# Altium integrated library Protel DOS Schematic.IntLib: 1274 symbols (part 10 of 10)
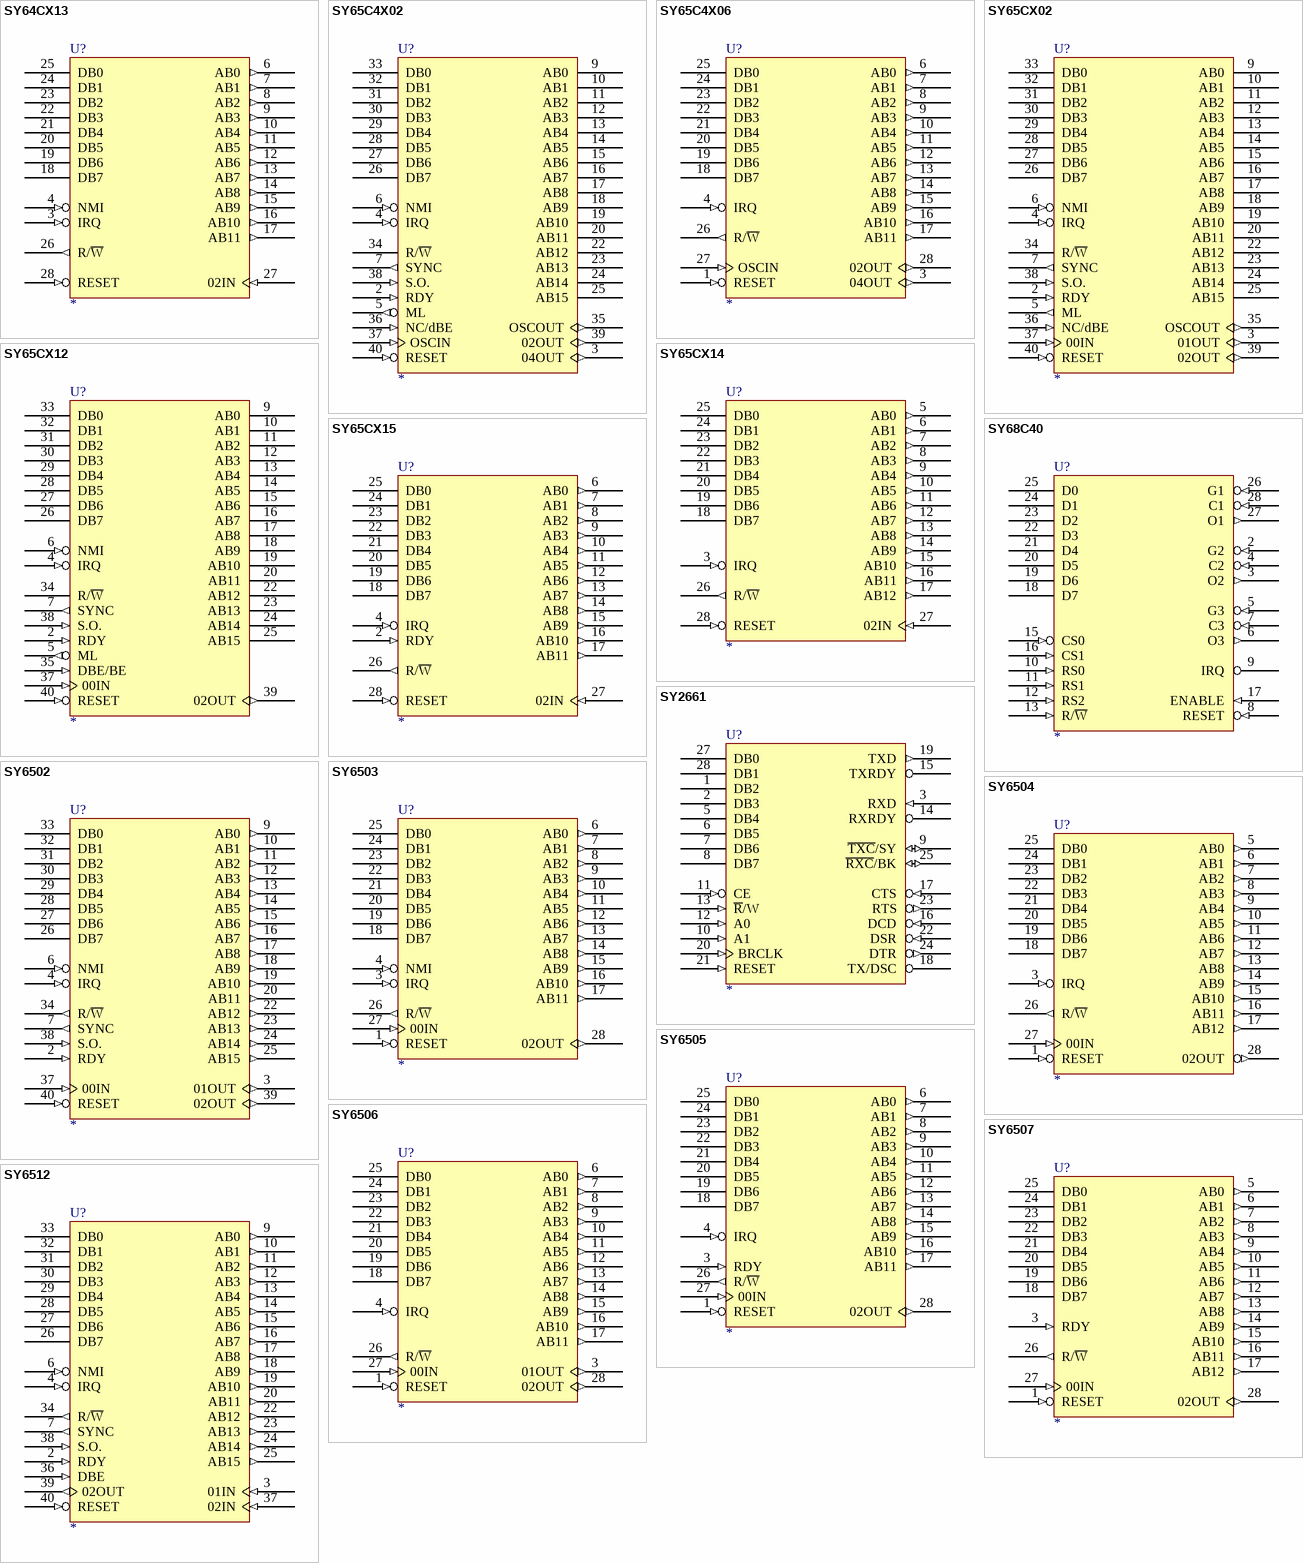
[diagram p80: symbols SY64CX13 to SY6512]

## SY6504
designator U?
footprint DIP-28
pins: 1 RESET (in), 2 GND (power) hidden to GND, 3 IRQ (in), 4 VCC (power) hidden to VCC, 5 AB0 (out), 6 AB1 (out), 7 AB2 (out), 8 AB3 (out), 9 AB4 (out), 10 AB5 (out), 11 AB6 (out), 12 AB7 (out), 13 AB8 (out), 14 AB9 (out), 15 AB10 (out), 16 AB11 (out), 17 AB12 (out), 18 DB7 (hiz), 19 DB6 (hiz), 20 DB5 (hiz), 21 DB4 (hiz), 22 DB3 (hiz), 23 DB2 (hiz), 24 DB1 (hiz), 25 DB0 (hiz), 26 R/~{W} (out), 27 00IN (in), 28 02OUT (out)
2 alternate drawings of the same symbol

## SY6505
designator U?
footprint DIP-28
pins: 1 RESET (in), 2 GND (power) hidden to GND, 3 RDY (in), 4 IRQ (in), 5 VCC (power) hidden to VCC, 6 AB0 (out), 7 AB1 (out), 8 AB2 (out), 9 AB3 (out), 10 AB4 (out), 11 AB5 (out), 12 AB6 (out), 13 AB7 (out), 14 AB8 (out), 15 AB9 (out), 16 AB10 (out), 17 AB11 (out), 18 DB7 (hiz), 19 DB6 (hiz), 20 DB5 (hiz), 21 DB4 (hiz), 22 DB3 (hiz), 23 DB2 (hiz), 24 DB1 (hiz), 25 DB0 (hiz), 26 R/~{W} (out), 27 00IN (in), 28 02OUT (out)
2 alternate drawings of the same symbol

## SY6506
designator U?
footprint DIP-28
pins: 1 RESET (in), 2 GND (power) hidden to GND, 3 01OUT (out), 4 IRQ (in), 5 VCC (power) hidden to VCC, 6 AB0 (out), 7 AB1 (out), 8 AB2 (out), 9 AB3 (out), 10 AB4 (out), 11 AB5 (out), 12 AB6 (out), 13 AB7 (out), 14 AB8 (out), 15 AB9 (out), 16 AB10 (out), 17 AB11 (out), 18 DB7 (hiz), 19 DB6 (hiz), 20 DB5 (hiz), 21 DB4 (hiz), 22 DB3 (hiz), 23 DB2 (hiz), 24 DB1 (hiz), 25 DB0 (hiz), 26 R/~{W} (out), 27 00IN (in), 28 02OUT (out)
2 alternate drawings of the same symbol

## SY6507
designator U?
footprint DIP-28
pins: 1 RESET (in), 2 GND (power) hidden to GND, 3 RDY (in), 4 VCC (power) hidden to VCC, 5 AB0 (out), 6 AB1 (out), 7 AB2 (out), 8 AB3 (out), 9 AB4 (out), 10 AB5 (out), 11 AB6 (out), 12 AB7 (out), 13 AB8 (out), 14 AB9 (out), 15 AB10 (out), 16 AB11 (out), 17 AB12 (out), 18 DB7 (hiz), 19 DB6 (hiz), 20 DB5 (hiz), 21 DB4 (hiz), 22 DB3 (hiz), 23 DB2 (hiz), 24 DB1 (hiz), 25 DB0 (hiz), 26 R/~{W} (out), 27 00IN (in), 28 02OUT (out)
2 alternate drawings of the same symbol

## SY6512
designator U?
footprint DIP-40
pins: 1 GND (power) hidden to GND, 2 RDY (in), 3 01IN (in), 4 IRQ (in), 5 GND (power) hidden to GND, 6 NMI (in), 7 SYNC (out), 8 VCC (power) hidden to VCC, 9 AB0 (out), 10 AB1 (out), 11 AB2 (out), 12 AB3 (out), 13 AB4 (out), 14 AB5 (out), 15 AB6 (out), 16 AB7 (out), 17 AB8 (out), 18 AB9 (out), 19 AB10 (out), 20 AB11 (out), 21 GND (power) hidden to GND, 22 AB12 (out), 23 AB13 (out), 24 AB14 (out), 25 AB15 (out), 26 DB7 (hiz), 27 DB6 (hiz), 28 DB5 (hiz), 29 DB4 (hiz), 30 DB3 (hiz), 31 DB2 (hiz), 32 DB1 (hiz), 33 DB0 (hiz), 34 R/~{W} (out), 36 DBE (in), 37 02IN (in), 38 S.O. (in), 39 02OUT (out), 40 RESET (in)
2 alternate drawings of the same symbol

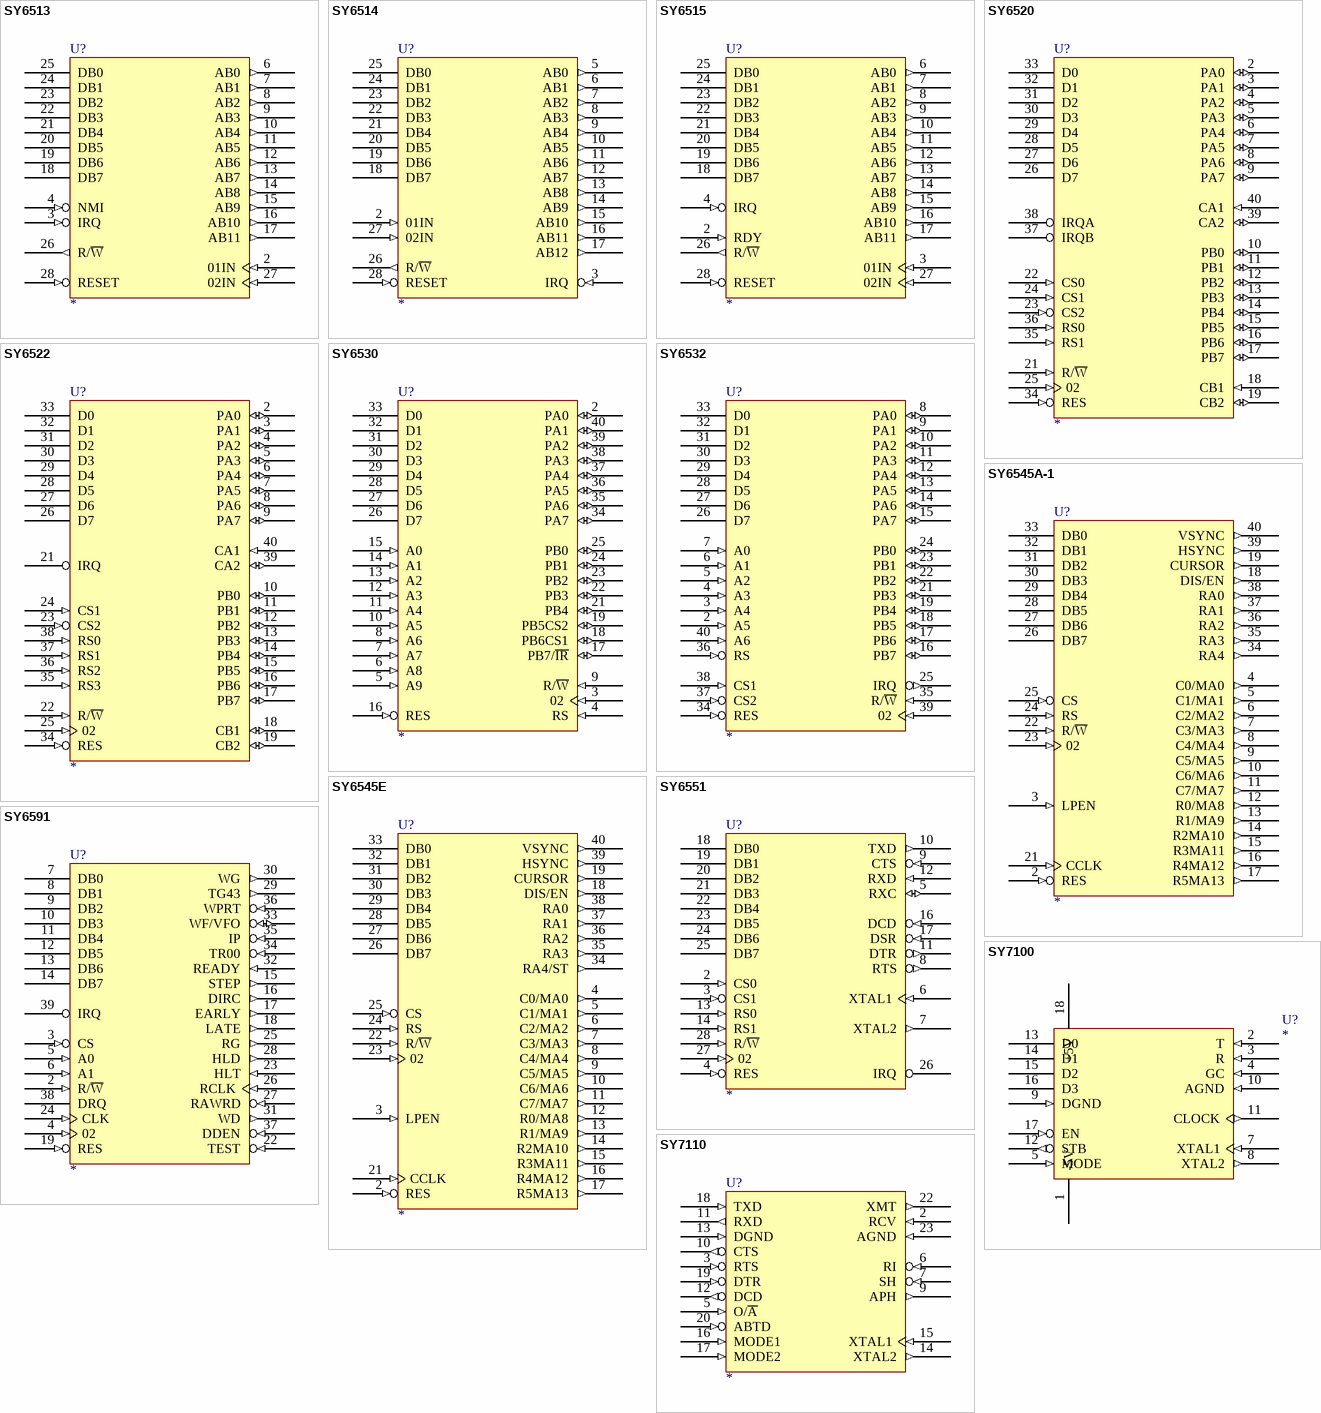
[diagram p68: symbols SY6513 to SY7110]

## SY6513
designator U?
footprint DIP-28
pins: 1 GND (power) hidden to GND, 2 01IN (in), 3 IRQ (in), 4 NMI (in), 5 VCC (power) hidden to VCC, 6 AB0 (out), 7 AB1 (out), 8 AB2 (out), 9 AB3 (out), 10 AB4 (out), 11 AB5 (out), 12 AB6 (out), 13 AB7 (out), 14 AB8 (out), 15 AB9 (out), 16 AB10 (out), 17 AB11 (out), 18 DB7 (hiz), 19 DB6 (hiz), 20 DB5 (hiz), 21 DB4 (hiz), 22 DB3 (hiz), 23 DB2 (hiz), 24 DB1 (hiz), 25 DB0 (hiz), 26 R/~{W} (out), 27 02IN (in), 28 RESET (in)
2 alternate drawings of the same symbol

## SY6514
designator U?
footprint DIP-28
pins: 1 GND (power) hidden to GND, 2 01IN (in), 3 IRQ (in), 4 VCC (power) hidden to VCC, 5 AB0 (out), 6 AB1 (out), 7 AB2 (out), 8 AB3 (out), 9 AB4 (out), 10 AB5 (out), 11 AB6 (out), 12 AB7 (out), 13 AB8 (out), 14 AB9 (out), 15 AB10 (out), 16 AB11 (out), 17 AB12 (out), 18 DB7 (hiz), 19 DB6 (hiz), 20 DB5 (hiz), 21 DB4 (hiz), 22 DB3 (hiz), 23 DB2 (hiz), 24 DB1 (hiz), 25 DB0 (hiz), 26 R/~{W} (out), 27 02IN (in), 28 RESET (in)
2 alternate drawings of the same symbol

## SY6515
designator U?
footprint DIP-28
pins: 1 GND (power) hidden to GND, 2 RDY (in), 3 01IN (in), 4 IRQ (in), 5 VCC (power) hidden to VCC, 6 AB0 (out), 7 AB1 (out), 8 AB2 (out), 9 AB3 (out), 10 AB4 (out), 11 AB5 (out), 12 AB6 (out), 13 AB7 (out), 14 AB8 (out), 15 AB9 (out), 16 AB10 (out), 17 AB11 (out), 18 DB7 (hiz), 19 DB6 (hiz), 20 DB5 (hiz), 21 DB4 (hiz), 22 DB3 (hiz), 23 DB2 (hiz), 24 DB1 (hiz), 25 DB0 (hiz), 26 R/~{W} (out), 27 02IN (in), 28 RESET (in)
2 alternate drawings of the same symbol

## SY6520
designator U?
footprint DIP-40
pins: 1 GND (power) hidden to GND, 2 PA0 (io), 3 PA1 (io), 4 PA2 (io), 5 PA3 (io), 6 PA4 (io), 7 PA5 (io), 8 PA6 (io), 9 PA7 (io), 10 PB0 (io), 11 PB1 (io), 12 PB2 (io), 13 PB3 (io), 14 PB4 (io), 15 PB5 (io), 16 PB6 (io), 17 PB7 (io), 18 CB1 (in), 19 CB2 (io), 20 VCC (power) hidden to VCC, 21 R/~{W} (in), 22 CS0 (in), 23 CS2 (in), 24 CS1 (in), 25 02 (in), 26 D7 (hiz), 27 D6 (hiz), 28 D5 (hiz), 29 D4 (hiz), 30 D3 (hiz), 31 D2 (hiz), 32 D1 (hiz), 33 D0 (hiz), 34 RES (in), 35 RS1 (in), 36 RS0 (in), 37 IRQB (oc), 38 IRQA (oc), 39 CA2 (io), 40 CA1 (in)
2 alternate drawings of the same symbol

## SY6522
designator U?
footprint DIP-40
pins: 1 GND (power) hidden to GND, 2 PA0 (io), 3 PA1 (io), 4 PA2 (io), 5 PA3 (io), 6 PA4 (io), 7 PA5 (io), 8 PA6 (io), 9 PA7 (io), 10 PB0 (io), 11 PB1 (io), 12 PB2 (io), 13 PB3 (io), 14 PB4 (io), 15 PB5 (io), 16 PB6 (io), 17 PB7 (io), 18 CB1 (io), 19 CB2 (io), 20 VCC (power) hidden to VCC, 21 IRQ (oc), 22 R/~{W} (in), 23 CS2 (in), 24 CS1 (in), 25 02 (in), 26 D7 (hiz), 27 D6 (hiz), 28 D5 (hiz), 29 D4 (hiz), 30 D3 (hiz), 31 D2 (hiz), 32 D1 (hiz), 33 D0 (hiz), 34 RES (in), 35 RS3 (in), 36 RS2 (in), 37 RS1 (in), 38 RS0 (in), 39 CA2 (io), 40 CA1 (in)
2 alternate drawings of the same symbol

## SY6530
designator U?
footprint DIP-40
pins: 1 GND (power) hidden to GND, 2 PA0 (io), 3 02 (in), 4 RS (in), 5 A9 (in), 6 A8 (in), 7 A7 (in), 8 A6 (in), 9 R/~{W} (in), 10 A5 (in), 11 A4 (in), 12 A3 (in), 13 A2 (in), 14 A1 (in), 15 A0 (in), 16 RES (in), 17 PB7/~{IR} (io), 18 PB6CS1 (io), 19 PB5CS2 (io), 20 VCC (power) hidden to VCC, 21 PB4 (io), 22 PB3 (io), 23 PB2 (io), 24 PB1 (io), 25 PB0 (io), 26 D7 (hiz), 27 D6 (hiz), 28 D5 (hiz), 29 D4 (hiz), 30 D3 (hiz), 31 D2 (hiz), 32 D1 (hiz), 33 D0 (hiz), 34 PA7 (io), 35 PA6 (io), 36 PA5 (io), 37 PA4 (io), 38 PA3 (io), 39 PA2 (io), 40 PA1 (io)
2 alternate drawings of the same symbol

## SY6532
designator U?
footprint DIP-40
pins: 1 GND (power) hidden to GND, 2 A5 (in), 3 A4 (in), 4 A3 (in), 5 A2 (in), 6 A1 (in), 7 A0 (in), 8 PA0 (io), 9 PA1 (io), 10 PA2 (io), 11 PA3 (io), 12 PA4 (io), 13 PA5 (io), 14 PA6 (io), 15 PA7 (io), 16 PB7 (io), 17 PB6 (io), 18 PB5 (io), 19 PB4 (io), 20 VCC (power) hidden to VCC, 21 PB3 (io), 22 PB2 (io), 23 PB1 (io), 24 PB0 (io), 25 IRQ (out), 26 D7 (hiz), 27 D6 (hiz), 28 D5 (hiz), 29 D4 (hiz), 30 D3 (hiz), 31 D2 (hiz), 32 D1 (hiz), 33 D0 (hiz), 34 RES (in), 35 R/~{W} (in), 36 RS (in), 37 CS2 (in), 38 CS1 (in), 39 02 (in), 40 A6 (in)
2 alternate drawings of the same symbol

## SY6545A-1
designator U?
footprint DIP-40
pins: 1 GND (power) hidden to GND, 2 RES (in), 3 LPEN (in), 4 C0/MA0 (out), 5 C1/MA1 (out), 6 C2/MA2 (out), 7 C3/MA3 (out), 8 C4/MA4 (out), 9 C5/MA5 (out), 10 C6/MA6 (out), 11 C7/MA7 (out), 12 R0/MA8 (out), 13 R1/MA9 (out), 14 R2MA10 (out), 15 R3MA11 (out), 16 R4MA12 (out), 17 R5MA13 (out), 18 DIS/EN (out), 19 CURSOR (out), 20 VCC (power) hidden to VCC, 21 CCLK (in), 22 R/~{W} (in), 23 02 (in), 24 RS (in), 25 CS (in), 26 DB7 (hiz), 27 DB6 (hiz), 28 DB5 (hiz), 29 DB4 (hiz), 30 DB3 (hiz), 31 DB2 (hiz), 32 DB1 (hiz), 33 DB0 (hiz), 34 RA4 (out), 35 RA3 (out), 36 RA2 (out), 37 RA1 (out), 38 RA0 (out), 39 HSYNC (out), 40 VSYNC (out)
2 alternate drawings of the same symbol

## SY6545E
designator U?
footprint DIP-40
pins: 1 GND (power) hidden to GND, 2 RES (in), 3 LPEN (in), 4 C0/MA0 (out), 5 C1/MA1 (out), 6 C2/MA2 (out), 7 C3/MA3 (out), 8 C4/MA4 (out), 9 C5/MA5 (out), 10 C6/MA6 (out), 11 C7/MA7 (out), 12 R0/MA8 (out), 13 R1/MA9 (out), 14 R2MA10 (out), 15 R3MA11 (out), 16 R4MA12 (out), 17 R5MA13 (out), 18 DIS/EN (out), 19 CURSOR (out), 20 VCC (power) hidden to VCC, 21 CCLK (in), 22 R/~{W} (in), 23 02 (in), 24 RS (in), 25 CS (in), 26 DB7 (hiz), 27 DB6 (hiz), 28 DB5 (hiz), 29 DB4 (hiz), 30 DB3 (hiz), 31 DB2 (hiz), 32 DB1 (hiz), 33 DB0 (hiz), 34 RA4/ST (out), 35 RA3 (out), 36 RA2 (out), 37 RA1 (out), 38 RA0 (out), 39 HSYNC (out), 40 VSYNC (out)
2 alternate drawings of the same symbol

## SY6551
designator U?
footprint DIP-28
pins: 1 GND (power) hidden to GND, 2 CS0 (in), 3 CS1 (in), 4 RES (in), 5 RXC (io), 6 XTAL1 (in), 7 XTAL2 (out), 8 RTS (out), 9 CTS (in), 10 TXD (out), 11 DTR (out), 12 RXD (in), 13 RS0 (in), 14 RS1 (in), 15 VCC (power) hidden to VCC, 16 DCD (in), 17 DSR (in), 18 DB0 (hiz), 19 DB1 (hiz), 20 DB2 (hiz), 21 DB3 (hiz), 22 DB4 (hiz), 23 DB5 (hiz), 24 DB6 (hiz), 25 DB7 (hiz), 26 IRQ (oc), 27 02 (in), 28 R/~{W} (in)
2 alternate drawings of the same symbol

## SY6591
designator U?
footprint DIP-40
pins: 2 R/~{W} (in), 3 CS (in), 4 02 (in), 5 A0 (in), 6 A1 (in), 7 DB0 (hiz), 8 DB1 (hiz), 9 DB2 (hiz), 10 DB3 (hiz), 11 DB4 (hiz), 12 DB5 (hiz), 13 DB6 (hiz), 14 DB7 (hiz), 15 STEP (out), 16 DIRC (out), 17 EARLY (out), 18 LATE (out), 19 RES (in), 20 GND (power) hidden to GND, 21 VCC (power) hidden to VCC, 22 TEST (in), 23 HLT (in), 24 CLK (in), 25 RG (out), 26 RCLK (in), 27 RAWRD (in), 28 HLD (out), 29 TG43 (out), 30 WG (out), 31 WD (out), 32 READY (in), 33 WF/VFO (io), 34 TR00 (in), 35 IP (in), 36 WPRT (in), 37 DDEN (in), 38 DRQ (oc), 39 IRQ (oc)
2 alternate drawings of the same symbol

## SY7100
designator U?
footprint DIP-18
pins: 1 -5V (power), 2 T (in), 3 R (in), 4 GC (in), 5 MODE (in), 7 XTAL1 (in), 8 XTAL2 (out), 9 DGND (in), 10 AGND (in), 11 CLOCK (out), 12 STB (out), 13 D0 (hiz), 14 D1 (hiz), 15 D2 (hiz), 16 D3 (hiz), 17 EN (in), 18 +5V (power)
2 alternate drawings of the same symbol

## SY7110
designator U?
footprint DIP-24
pins: 2 RCV (in), 3 RTS (in), 5 O/~{A} (in), 6 RI (in), 7 SH (in), 8 VCC (power) hidden to VCC, 9 APH (out), 10 CTS (out), 11 RXD (out), 12 DCD (out), 13 DGND (in), 14 XTAL2 (out), 15 XTAL1 (in), 16 MODE1 (in), 17 MODE2 (in), 18 TXD (in), 19 DTR (in), 20 ABTD (in), 22 XMT (out), 23 AGND (in), 24 GND (power) hidden to GND
2 alternate drawings of the same symbol


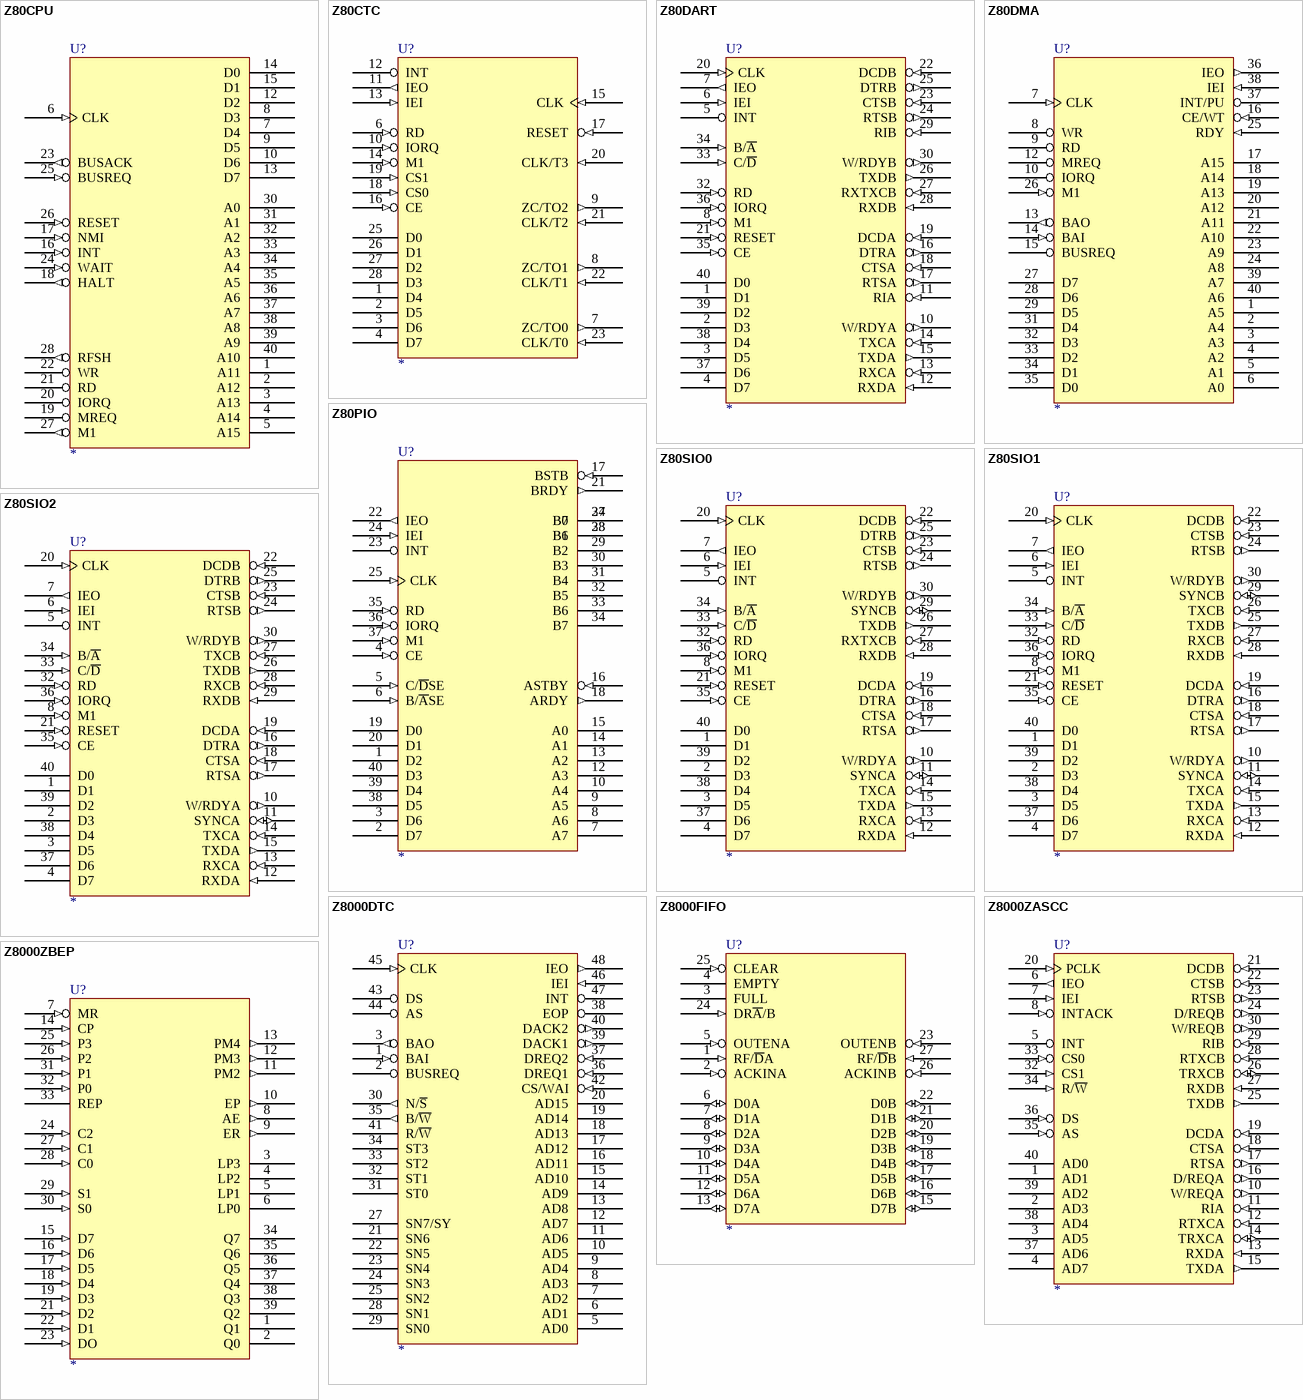
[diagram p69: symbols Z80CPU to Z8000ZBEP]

## Z80CPU
designator U?
footprint DIP-40
pins: 1 A11 (hiz), 2 A12 (hiz), 3 A13 (hiz), 4 A14 (hiz), 5 A15 (hiz), 6 CLK (in), 7 D4 (hiz), 8 D3 (hiz), 9 D5 (hiz), 10 D6 (hiz), 11 VCC (power) hidden to VCC, 12 D2 (hiz), 13 D7 (hiz), 14 D0 (hiz), 15 D1 (hiz), 16 INT (in), 17 NMI (in), 18 HALT (out), 19 MREQ (hiz), 20 IORQ (hiz), 21 RD (hiz), 22 WR (hiz), 23 BUSACK (out), 24 WAIT (in), 25 BUSREQ (in), 26 RESET (in), 27 M1 (out), 28 RFSH (out), 29 GND (power) hidden to GND, 30 A0 (hiz), 31 A1 (hiz), 32 A2 (hiz), 33 A3 (hiz), 34 A4 (hiz), 35 A5 (hiz), 36 A6 (hiz), 37 A7 (hiz), 38 A8 (hiz), 39 A9 (hiz), 40 A10 (hiz)
2 alternate drawings of the same symbol

## Z80CTC
designator U?
footprint DIP-28
pins: 1 D4 (hiz), 2 D5 (hiz), 3 D6 (hiz), 4 D7 (hiz), 5 GND (power) hidden to GND, 6 RD (in), 7 ZC/TO0 (out), 8 ZC/TO1 (out), 9 ZC/TO2 (out), 10 IORQ (in), 11 IEO (out), 12 INT (oc), 13 IEI (in), 14 M1 (in), 15 CLK (in), 16 CE (in), 17 RESET (in), 18 CS0 (in), 19 CS1 (in), 20 CLK/T3 (in), 21 CLK/T2 (in), 22 CLK/T1 (in), 23 CLK/T0 (in), 24 VCC (power) hidden to VCC, 25 D0 (hiz), 26 D1 (hiz), 27 D2 (hiz), 28 D3 (hiz)
2 alternate drawings of the same symbol

## Z80DART
designator U?
footprint DIP-40
pins: 1 D1 (hiz), 2 D3 (hiz), 3 D5 (hiz), 4 D7 (hiz), 5 INT (oc), 6 IEI (in), 7 IEO (out), 8 M1 (in), 9 VCC (power) hidden to VCC, 10 W/RDYA (out), 11 RIA (in), 12 RXDA (in), 13 RXCA (in), 14 TXCA (in), 15 TXDA (out), 16 DTRA (out), 17 RTSA (out), 18 CTSA (in), 19 DCDA (in), 20 CLK (in), 21 RESET (in), 22 DCDB (in), 23 CTSB (in), 24 RTSB (out), 25 DTRB (out), 26 TXDB (out), 27 RXTXCB (in), 28 RXDB (in), 29 RIB (in), 30 W/RDYB (out), 31 GND (power) hidden to GND, 32 RD (in), 33 C/~{D} (in), 34 B/~{A} (in), 35 CE (in), 36 IORQ (in), 37 D6 (hiz), 38 D4 (hiz), 39 D2 (hiz), 40 D0 (hiz)
2 alternate drawings of the same symbol

## Z80DMA
designator U?
footprint DIP-40
pins: 1 A5 (hiz), 2 A4 (hiz), 3 A3 (hiz), 4 A2 (hiz), 5 A1 (hiz), 6 A0 (hiz), 7 CLK (in), 8 WR (hiz), 9 RD (hiz), 10 IORQ (hiz), 11 VCC (power) hidden to VCC, 12 MREQ (hiz), 13 BAO (out), 14 BAI (in), 15 BUSREQ (oc), 16 CE/WT (in), 17 A15 (hiz), 18 A14 (hiz), 19 A13 (hiz), 20 A12 (hiz), 21 A11 (hiz), 22 A10 (hiz), 23 A9 (hiz), 24 A8 (hiz), 25 RDY (in), 26 M1 (in), 27 D7 (hiz), 28 D6 (hiz), 29 D5 (hiz), 30 GND (power) hidden to GND, 31 D4 (hiz), 32 D3 (hiz), 33 D2 (hiz), 34 D1 (hiz), 35 D0 (hiz), 36 IEO (out), 37 INT/PU (oc), 38 IEI (in), 39 A7 (hiz), 40 A6 (hiz)
2 alternate drawings of the same symbol

## Z80PIO
designator U?
footprint DIP-40
pins: 1 D2 (hiz), 2 D7 (hiz), 3 D6 (hiz), 4 CE (in), 5 C/~{D}SE (in), 6 B/~{A}SE (in), 7 A7 (hiz), 8 A6 (hiz), 9 A5 (hiz), 10 A4 (hiz), 11 GND (power) hidden to GND, 12 A3 (hiz), 13 A2 (hiz), 14 A1 (hiz), 15 A0 (hiz), 16 ASTBY (in), 17 BSTB (in), 18 ARDY (out), 19 D0 (hiz), 20 D1 (hiz), 21 BRDY (out), 22 IEO (out), 23 INT (oc), 24 IEI (in), 25 CLK (in), 26 VCC (power) hidden to VCC, 27 B0 (hiz), 28 B1 (hiz), 29 B2 (hiz), 30 B3 (hiz), 31 B4 (hiz), 32 B5 (hiz), 33 B6 (hiz), 33 B6 (hiz), 34 B7 (hiz), 34 B7 (hiz), 35 RD (in), 36 IORQ (in), 37 M1 (in), 38 D5 (hiz), 39 D4 (hiz), 40 D3 (hiz)
2 alternate drawings of the same symbol

## Z80SIO0
designator U?
footprint DIP-40
pins: 1 D1 (hiz), 2 D3 (hiz), 3 D5 (hiz), 4 D7 (hiz), 5 INT (oc), 6 IEI (in), 7 IEO (out), 8 M1 (in), 9 VCC (power) hidden to VCC, 10 W/RDYA (out), 11 SYNCA (io), 12 RXDA (in), 13 RXCA (in), 14 TXCA (in), 15 TXDA (out), 16 DTRA (out), 17 RTSA (out), 18 CTSA (in), 19 DCDA (in), 20 CLK (in), 21 RESET (in), 22 DCDB (in), 23 CTSB (in), 24 RTSB (out), 25 DTRB (out), 26 TXDB (out), 27 RXTXCB (in), 28 RXDB (in), 29 SYNCB (io), 30 W/RDYB (out), 31 GND (power) hidden to GND, 32 RD (in), 33 C/~{D} (in), 34 B/~{A} (in), 35 CE (in), 36 IORQ (in), 37 D6 (hiz), 38 D4 (hiz), 39 D2 (hiz), 40 D0 (hiz)
2 alternate drawings of the same symbol

## Z80SIO1
designator U?
footprint DIP-40
pins: 1 D1 (hiz), 2 D3 (hiz), 3 D5 (hiz), 4 D7 (hiz), 5 INT (oc), 6 IEI (in), 7 IEO (out), 8 M1 (in), 9 VCC (power) hidden to VCC, 10 W/RDYA (out), 11 SYNCA (io), 12 RXDA (in), 13 RXCA (in), 14 TXCA (in), 15 TXDA (out), 16 DTRA (out), 17 RTSA (out), 18 CTSA (in), 19 DCDA (in), 20 CLK (in), 21 RESET (in), 22 DCDB (in), 23 CTSB (in), 24 RTSB (out), 25 TXDB (out), 26 TXCB (in), 27 RXCB (in), 28 RXDB (in), 29 SYNCB (io), 30 W/RDYB (out), 31 GND (power) hidden to GND, 32 RD (in), 33 C/~{D} (in), 34 B/~{A} (in), 35 CE (in), 36 IORQ (in), 37 D6 (hiz), 38 D4 (hiz), 39 D2 (hiz), 40 D0 (hiz)
2 alternate drawings of the same symbol

## Z80SIO2
designator U?
footprint DIP-40
pins: 1 D1 (hiz), 2 D3 (hiz), 3 D5 (hiz), 4 D7 (hiz), 5 INT (oc), 6 IEI (in), 7 IEO (out), 8 M1 (in), 9 VCC (power) hidden to VCC, 10 W/RDYA (out), 11 SYNCA (io), 12 RXDA (in), 13 RXCA (in), 14 TXCA (in), 15 TXDA (out), 16 DTRA (out), 17 RTSA (out), 18 CTSA (in), 19 DCDA (in), 20 CLK (in), 21 RESET (in), 22 DCDB (in), 23 CTSB (in), 24 RTSB (out), 25 DTRB (out), 26 TXDB (out), 27 TXCB (in), 28 RXCB (in), 29 RXDB (in), 30 W/RDYB (out), 31 GND (power) hidden to GND, 32 RD (in), 33 C/~{D} (in), 34 B/~{A} (in), 35 CE (in), 36 IORQ (in), 37 D6 (hiz), 38 D4 (hiz), 39 D2 (hiz), 40 D0 (hiz)
2 alternate drawings of the same symbol

## Z8000DTC
designator U?
footprint DIP-48
pins: 1 BAI (in), 2 BUSREQ (hiz), 3 BAO (out), 4 VCC (power) hidden to VCC, 5 AD0 (hiz), 6 AD1 (hiz), 7 AD2 (hiz), 8 AD3 (hiz), 9 AD4 (hiz), 10 AD5 (hiz), 11 AD6 (hiz), 12 AD7 (hiz), 13 AD8 (hiz), 14 AD9 (hiz), 15 AD10 (hiz), 16 AD11 (hiz), 17 AD12 (hiz), 18 AD13 (hiz), 19 AD14 (hiz), 20 AD15 (hiz), 21 SN6 (hiz), 22 SN5 (hiz), 23 SN4 (hiz), 24 SN3 (hiz), 25 SN2 (hiz), 26 GND (power) hidden to GND, 27 SN7/SY (hiz), 28 SN1 (hiz), 29 SN0 (hiz), 30 N/~{S} (out), 31 ST0 (hiz), 32 ST1 (hiz), 33 ST2 (hiz), 34 ST3 (hiz), 35 B/~{W} (out), 36 DREQ1 (in), 37 DREQ2 (in), 38 EOP (hiz), 39 DACK1 (out), 40 DACK2 (out), 41 R/~{W} (hiz), 42 CS/WAI (in), 43 DS (hiz), 44 AS (hiz), 45 CLK (in), 46 IEI (in), 47 INT (oc), 48 IEO (out)
2 alternate drawings of the same symbol

## Z8000FIFO
designator U?
footprint DIP-28
pins: 1 RF/~{D}A (in), 2 ACKINA (in), 3 FULL (oc), 4 EMPTY (oc), 5 OUTENA (in), 6 D0A (io), 7 D1A (io), 8 D2A (io), 9 D3A (io), 10 D4A (io), 11 D5A (io), 12 D6A (io), 13 D7A (io), 14 GND (power) hidden to GND, 15 D7B (io), 16 D6B (io), 17 D5B (io), 18 D4B (io), 19 D3B (io), 20 D2B (io), 21 D1B (io), 22 D0B (io), 23 OUTENB (in), 24 DR~{A}/B (in), 25 CLEAR (in), 26 ACKINB (in), 27 RF/~{D}B (in), 28 VCC (power) hidden to VCC
2 alternate drawings of the same symbol

## Z8000ZASCC
designator U?
footprint DIP-40
pins: 1 AD1 (hiz), 2 AD3 (hiz), 3 AD5 (hiz), 4 AD7 (hiz), 5 INT (oc), 6 IEO (out), 7 IEI (in), 8 INTACK (in), 9 VCC (power) hidden to VCC, 10 W/REQA (out), 11 RIA (in), 12 RTXCA (in), 13 RXDA (in), 14 TRXCA (io), 15 TXDA (out), 16 D/REQA (out), 17 RTSA (out), 18 CTSA (in), 19 DCDA (in), 20 PCLK (in), 21 DCDB (in), 22 CTSB (in), 23 RTSB (out), 24 D/REQB (out), 25 TXDB (out), 26 TRXCB (io), 27 RXDB (in), 28 RTXCB (in), 29 RIB (in), 30 W/REQB (out), 31 GND (power) hidden to GND, 32 CS1 (in), 33 CS0 (in), 34 R/~{W} (in), 35 AS (in), 36 DS (in), 37 AD6 (hiz), 38 AD4 (hiz), 39 AD2 (hiz), 40 AD0 (hiz)
2 alternate drawings of the same symbol

## Z8000ZBEP
designator U?
footprint DIP-40
pins: 1 Q1 (hiz), 2 Q0 (hiz), 3 LP3 (hiz), 4 LP2 (hiz), 5 LP1 (hiz), 6 LP0 (hiz), 7 MR (in), 8 AE (out), 9 ER (out), 10 EP (out), 11 PM2 (out), 12 PM3 (out), 13 PM4 (out), 14 CP (in), 15 D7 (in), 16 D6 (in), 17 D5 (in), 18 D4 (in), 19 D3 (in), 20 GND (power) hidden to GND, 21 D2 (in), 22 D1 (in), 23 DO (in), 24 C2 (in), 25 P3 (in), 26 P2 (in), 27 C1 (in), 28 C0 (in), 29 S1 (in), 30 S0 (in), 31 P1 (in), 32 P0 (in), 33 REP (hiz), 34 Q7 (hiz), 35 Q6 (hiz), 36 Q5 (hiz), 37 Q4 (hiz), 38 Q3 (hiz), 39 Q2 (hiz), 40 VCC (power) hidden to VCC
2 alternate drawings of the same symbol

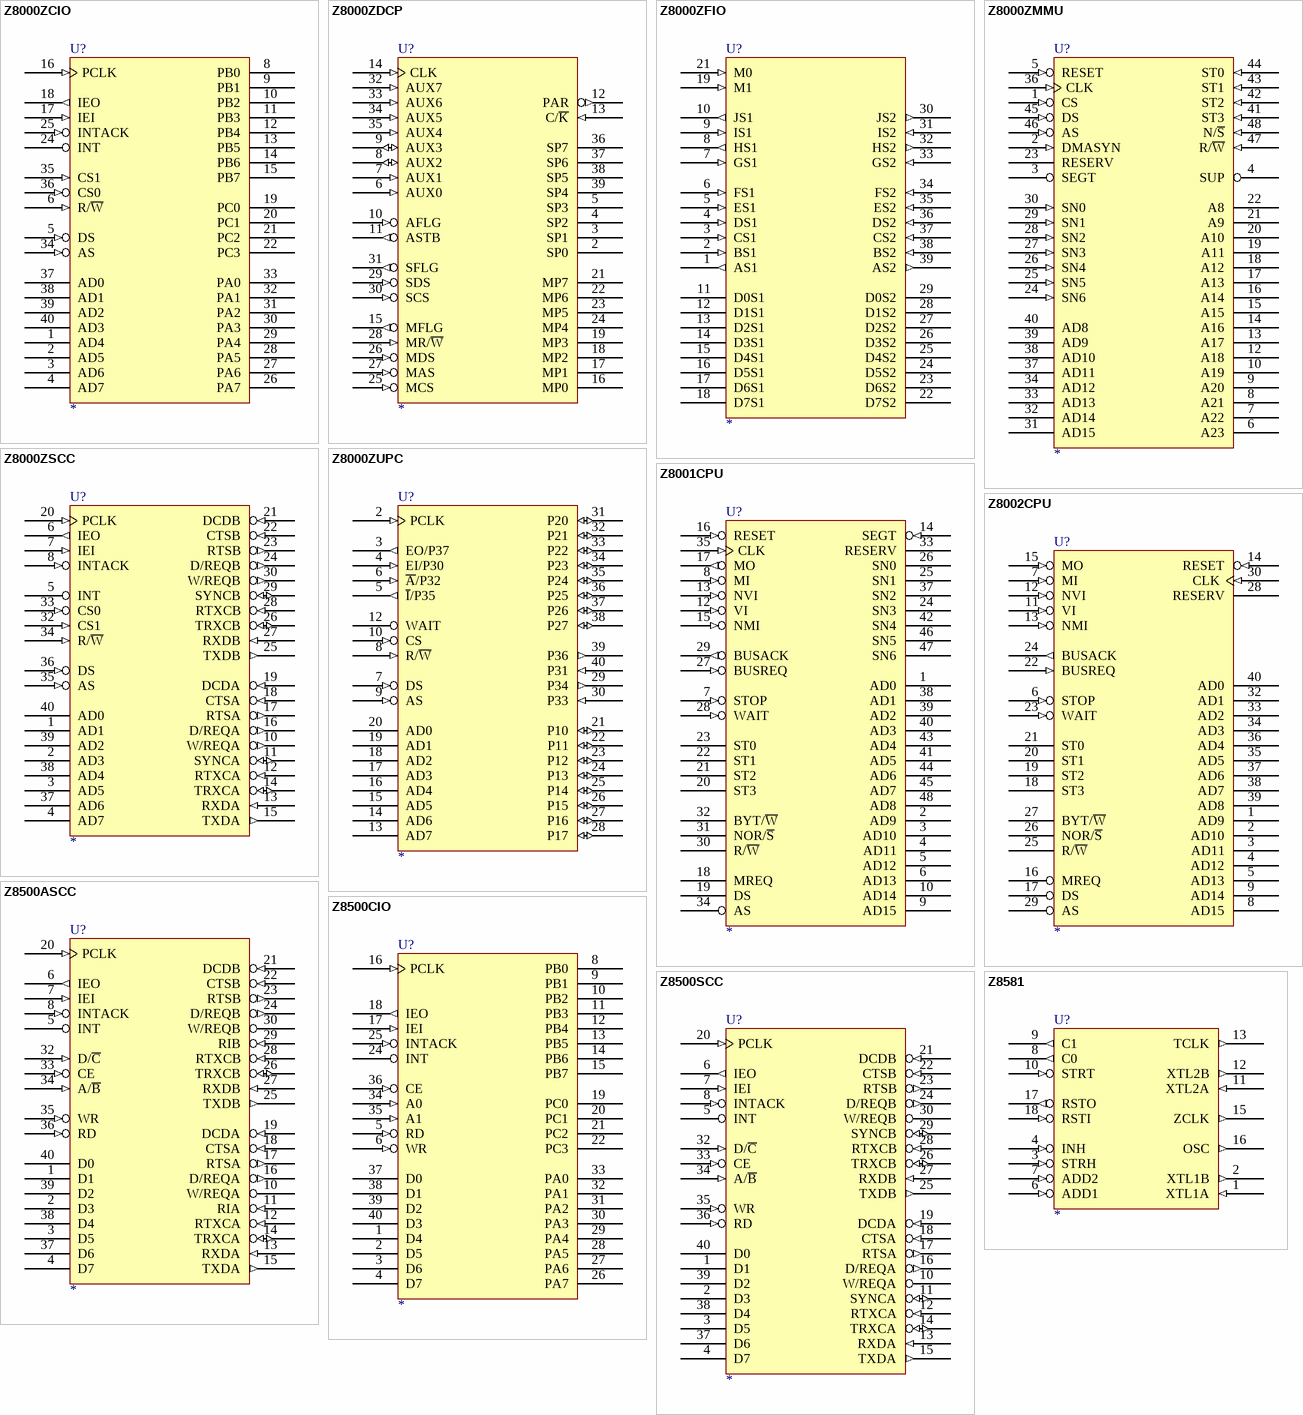
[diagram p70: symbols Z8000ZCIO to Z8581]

## Z8000ZCIO
designator U?
footprint DIP-40
pins: 1 AD4 (hiz), 2 AD5 (hiz), 3 AD6 (hiz), 4 AD7 (hiz), 5 DS (in), 6 R/~{W} (in), 7 GND (power) hidden to GND, 8 PB0 (hiz), 9 PB1 (hiz), 10 PB2 (hiz), 11 PB3 (hiz), 12 PB4 (hiz), 13 PB5 (hiz), 14 PB6 (hiz), 15 PB7 (hiz), 16 PCLK (in), 17 IEI (in), 18 IEO (out), 19 PC0 (hiz), 20 PC1 (hiz), 21 PC2 (hiz), 22 PC3 (hiz), 23 VCC (power) hidden to VCC, 24 INT (oc), 25 INTACK (in), 26 PA7 (hiz), 27 PA6 (hiz), 28 PA5 (hiz), 29 PA4 (hiz), 30 PA3 (hiz), 31 PA2 (hiz), 32 PA1 (hiz), 33 PA0 (hiz), 34 AS (in), 35 CS1 (in), 36 CS0 (in), 37 AD0 (hiz), 38 AD1 (hiz), 39 AD2 (hiz), 40 AD3 (hiz)
2 alternate drawings of the same symbol

## Z8000ZDCP
designator U?
footprint DIP-40
pins: 1 GND (power) hidden to GND, 2 SP0 (hiz), 3 SP1 (hiz), 4 SP2 (hiz), 5 SP3 (hiz), 6 AUX0 (in), 7 AUX1 (in), 8 AUX2 (io), 9 AUX3 (io), 10 AFLG (in), 11 ASTB (out), 12 PAR (out), 13 C/~{K} (in), 14 CLK (in), 15 MFLG (out), 16 MP0 (hiz), 17 MP1 (hiz), 18 MP2 (hiz), 19 MP3 (hiz), 20 GND (power) hidden to GND, 21 MP7 (hiz), 22 MP6 (hiz), 23 MP5 (hiz), 24 MP4 (hiz), 25 MCS (in), 26 MDS (in), 27 MAS (in), 28 MR/~{W} (in), 29 SDS (in), 30 SCS (in), 31 SFLG (out), 32 AUX7 (in), 33 AUX6 (in), 34 AUX5 (in), 35 AUX4 (in), 36 SP7 (hiz), 37 SP6 (hiz), 38 SP5 (hiz), 39 SP4 (hiz), 40 VCC (power) hidden to VCC
2 alternate drawings of the same symbol

## Z8000ZFIO
designator U?
footprint DIP-40
pins: 1 AS1 (out), 2 BS1 (in), 3 CS1 (in), 4 DS1 (in), 5 ES1 (in), 6 FS1 (in), 7 GS1 (in), 8 HS1 (out), 9 IS1 (in), 10 JS1 (out), 11 D0S1 (hiz), 12 D1S1 (hiz), 13 D2S1 (hiz), 14 D3S1 (hiz), 15 D4S1 (hiz), 16 D5S1 (hiz), 17 D6S1 (hiz), 18 D7S1 (hiz), 19 M1 (in), 20 GND (power) hidden to GND, 21 M0 (in), 22 D7S2 (hiz), 23 D6S2 (hiz), 24 D5S2 (hiz), 25 D4S2 (hiz), 26 D3S2 (hiz), 27 D2S2 (hiz), 28 D1S2 (hiz), 29 D0S2 (hiz), 30 JS2 (out), 31 IS2 (in), 32 HS2 (out), 33 GS2 (in), 34 FS2 (in), 35 ES2 (in), 36 DS2 (in), 37 CS2 (in), 38 BS2 (in), 39 AS2 (out), 40 VCC (power) hidden to VCC
2 alternate drawings of the same symbol

## Z8000ZMMU
designator U?
footprint DIP-48
pins: 1 CS (in), 2 DMASYN (in), 3 SEGT (oc), 4 SUP (oc), 5 RESET (in), 6 A23 (hiz), 7 A22 (hiz), 8 A21 (hiz), 9 A20 (hiz), 10 A19 (hiz), 11 VCC (power) hidden to VCC, 12 A18 (hiz), 13 A17 (hiz), 14 A16 (hiz), 15 A15 (hiz), 16 A14 (hiz), 17 A13 (hiz), 18 A12 (hiz), 19 A11 (hiz), 20 A10 (hiz), 21 A9 (hiz), 22 A8 (hiz), 23 RESERV, 24 SN6 (in), 25 SN5 (in), 26 SN4 (in), 27 SN3 (in), 28 SN2 (in), 29 SN1 (in), 30 SN0 (in), 31 AD15 (hiz), 32 AD14 (hiz), 33 AD13 (hiz), 34 AD12 (hiz), 35 GND (power) hidden to GND, 36 CLK (in), 37 AD11 (hiz), 38 AD10 (hiz), 39 AD9 (hiz), 40 AD8 (hiz), 41 ST3 (in), 42 ST2 (in), 43 ST1 (in), 44 ST0 (in), 45 DS (in), 46 AS (in), 47 R/~{W} (in), 48 N/~{S} (in)
2 alternate drawings of the same symbol

## Z8000ZSCC
designator U?
footprint DIP-40
pins: 1 AD1 (hiz), 2 AD3 (hiz), 3 AD5 (hiz), 4 AD7 (hiz), 5 INT (oc), 6 IEO (out), 7 IEI (in), 8 INTACK (in), 9 VCC (power) hidden to VCC, 10 W/REQA (out), 11 SYNCA (io), 12 RTXCA (in), 13 RXDA (in), 14 TRXCA (io), 15 TXDA (out), 16 D/REQA (out), 17 RTSA (out), 18 CTSA (in), 19 DCDA (in), 20 PCLK (in), 21 DCDB (in), 22 CTSB (in), 23 RTSB (out), 24 D/REQB (out), 25 TXDB (out), 26 TRXCB (io), 27 RXDB (in), 28 RTXCB (in), 29 SYNCB (io), 30 W/REQB (out), 31 GND (power) hidden to GND, 32 CS1 (in), 33 CS0 (in), 34 R/~{W} (in), 35 AS (in), 36 DS (in), 37 AD6 (hiz), 38 AD4 (hiz), 39 AD2 (hiz), 40 AD0 (hiz)
2 alternate drawings of the same symbol

## Z8000ZUPC
designator U?
footprint DIP-40
pins: 1 VCC (power) hidden to VCC, 2 PCLK (in), 3 EO/P37 (out), 4 EI/P30 (in), 5 ~{I}/P35 (out), 6 ~{A}/P32 (in), 7 DS (in), 8 R/~{W} (in), 9 AS (in), 10 CS (in), 11 GND (power) hidden to GND, 12 WAIT (oc), 13 AD7 (hiz), 14 AD6 (hiz), 15 AD5 (hiz), 16 AD4 (hiz), 17 AD3 (hiz), 18 AD2 (hiz), 19 AD1 (hiz), 20 AD0 (hiz), 21 P10 (io), 22 P11 (io), 23 P12 (io), 24 P13 (io), 25 P14 (io), 26 P15 (io), 27 P16 (io), 28 P17 (io), 29 P34 (out), 30 P33 (in), 31 P20 (io), 32 P21 (io), 33 P22 (io), 34 P23 (io), 35 P24 (io), 36 P25 (io), 37 P26 (io), 38 P27 (io), 39 P36 (out), 40 P31 (in)
2 alternate drawings of the same symbol

## Z8001CPU
designator U?
footprint DIP-48
pins: 1 AD0 (hiz), 2 AD9 (hiz), 3 AD10 (hiz), 4 AD11 (hiz), 5 AD12 (hiz), 6 AD13 (hiz), 7 STOP (in), 8 MI (in), 9 AD15 (hiz), 10 AD14 (hiz), 11 VCC (power) hidden to VCC, 12 VI (in), 13 NVI (in), 14 SEGT (in), 15 NMI (in), 16 RESET (in), 17 MO (out), 18 MREQ (hiz), 19 DS (hiz), 20 ST3 (hiz), 21 ST2 (hiz), 22 ST1 (hiz), 23 ST0 (hiz), 24 SN3 (hiz), 25 SN1 (hiz), 26 SN0 (hiz), 27 BUSREQ (in), 28 WAIT (in), 29 BUSACK (out), 30 R/~{W} (hiz), 31 NOR/~{S} (hiz), 32 BYT/~{W} (hiz), 33 RESERV, 34 AS (hiz), 35 CLK (in), 36 GND (power) hidden to GND, 37 SN2 (hiz), 38 AD1 (hiz), 39 AD2 (hiz), 40 AD3 (hiz), 41 AD5 (hiz), 42 SN4 (hiz), 43 AD4 (hiz), 44 AD6 (hiz), 45 AD7 (hiz), 46 SN5 (hiz), 47 SN6 (hiz), 48 AD8 (hiz)
2 alternate drawings of the same symbol

## Z8002CPU
designator U?
footprint DIP-40
pins: 1 AD9 (hiz), 2 AD10 (hiz), 3 AD11 (hiz), 4 AD12 (hiz), 5 AD13 (hiz), 6 STOP (in), 7 MI (in), 8 AD15 (hiz), 9 AD14 (hiz), 10 VCC (power) hidden to VCC, 11 VI (in), 12 NVI (in), 13 NMI (in), 14 RESET (in), 15 MO (in), 16 MREQ (hiz), 17 DS (hiz), 18 ST3 (hiz), 19 ST2 (hiz), 20 ST1 (hiz), 21 ST0 (hiz), 22 BUSREQ (in), 23 WAIT (in), 24 BUSACK (out), 25 R/~{W} (hiz), 26 NOR/~{S} (hiz), 27 BYT/~{W} (hiz), 28 RESERV, 29 AS (hiz), 30 CLK (in), 31 GND (power) hidden to GND, 32 AD1 (hiz), 33 AD2 (hiz), 34 AD3 (hiz), 35 AD5 (hiz), 36 AD4 (hiz), 37 AD6 (hiz), 38 AD7 (hiz), 39 AD8 (hiz), 40 AD0 (hiz)
2 alternate drawings of the same symbol

## Z8500ASCC
designator U?
footprint DIP-40
pins: 1 D1 (hiz), 2 D3 (hiz), 3 D5 (hiz), 4 D7 (hiz), 5 INT (oc), 6 IEO (out), 7 IEI (in), 8 INTACK (in), 9 VCC (power) hidden to VCC, 10 W/REQA (oc), 11 RIA (in), 12 RTXCA (in), 13 RXDA (in), 14 TRXCA (io), 15 TXDA (out), 16 D/REQA (out), 17 RTSA (out), 18 CTSA (in), 19 DCDA (in), 20 PCLK (in), 21 DCDB (in), 22 CTSB (in), 23 RTSB (out), 24 D/REQB (out), 25 TXDB (out), 26 TRXCB (io), 27 RXDB (in), 28 RTXCB (in), 29 RIB (in), 30 W/REQB (oc), 31 GND (power) hidden to GND, 32 D/~{C} (in), 33 CE (in), 34 A/~{B} (in), 35 WR (in), 36 RD (in), 37 D6 (hiz), 38 D4 (hiz), 39 D2 (hiz), 40 D0 (hiz)
2 alternate drawings of the same symbol

## Z8500CIO
designator U?
footprint DIP-40
pins: 1 D4 (hiz), 2 D5 (hiz), 3 D6 (hiz), 4 D7 (hiz), 5 RD (in), 6 WR (in), 7 GND (power) hidden to GND, 8 PB0 (hiz), 9 PB1 (hiz), 10 PB2 (hiz), 11 PB3 (hiz), 12 PB4 (hiz), 13 PB5 (hiz), 14 PB6 (hiz), 15 PB7 (hiz), 16 PCLK (in), 17 IEI (in), 18 IEO (out), 19 PC0 (hiz), 20 PC1 (hiz), 21 PC2 (hiz), 22 PC3 (hiz), 23 VCC (power) hidden to VCC, 24 INT (oc), 25 INTACK (in), 26 PA7 (hiz), 27 PA6 (hiz), 28 PA5 (hiz), 29 PA4 (hiz), 30 PA3 (hiz), 31 PA2 (hiz), 32 PA1 (hiz), 33 PA0 (hiz), 34 A0 (in), 35 A1 (in), 36 CE (in), 37 D0 (hiz), 38 D1 (hiz), 39 D2 (hiz), 40 D3 (hiz)
2 alternate drawings of the same symbol

## Z8500SCC
designator U?
footprint DIP-40
pins: 1 D1 (hiz), 2 D3 (hiz), 3 D5 (hiz), 4 D7 (hiz), 5 INT (oc), 6 IEO (out), 7 IEI (in), 8 INTACK (in), 9 VCC (power) hidden to VCC, 10 W/REQA (oc), 11 SYNCA (io), 12 RTXCA (in), 13 RXDA (in), 14 TRXCA (io), 15 TXDA (out), 16 D/REQA (out), 17 RTSA (out), 18 CTSA (in), 19 DCDA (in), 20 PCLK (in), 21 DCDB (in), 22 CTSB (in), 23 RTSB (out), 24 D/REQB (out), 25 TXDB (out), 26 TRXCB (io), 27 RXDB (in), 28 RTXCB (in), 29 SYNCB (io), 30 W/REQB (oc), 31 GND (power) hidden to GND, 32 D/~{C} (in), 33 CE (in), 34 A/~{B} (in), 35 WR (in), 36 RD (in), 37 D6 (hiz), 38 D4 (hiz), 39 D2 (hiz), 40 D0 (hiz)
2 alternate drawings of the same symbol

## Z8581
designator U?
footprint DIP-18
pins: 1 XTL1A (in), 2 XTL1B (out), 3 STRH (in), 4 INH (in), 5 VCC (power) hidden to VCC, 6 ADD1 (in), 7 ADD2 (in), 8 C0 (out), 9 C1 (out), 10 STRT (in), 11 XTL2A (in), 12 XTL2B (out), 13 TCLK (out), 14 GND (power) hidden to GND, 15 ZCLK (out), 16 OSC (out), 17 RSTO (out), 18 RSTI (in)
2 alternate drawings of the same symbol

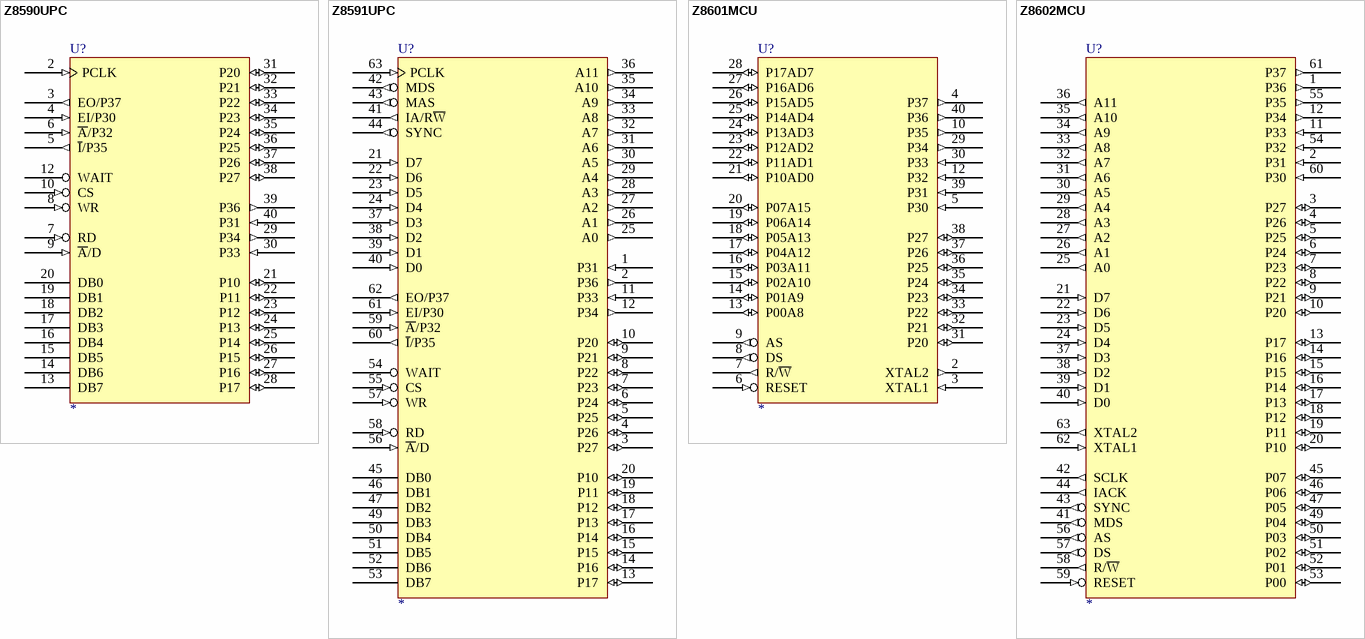
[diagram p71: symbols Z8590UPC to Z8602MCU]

## Z8590UPC
designator U?
footprint DIP-40
pins: 1 VCC (power) hidden to VCC, 2 PCLK (in), 3 EO/P37 (out), 4 EI/P30 (in), 5 ~{I}/P35 (out), 6 ~{A}/P32 (in), 7 RD (in), 8 WR (in), 9 ~{A}/D (in), 10 CS (in), 11 GND (power) hidden to GND, 12 WAIT (oc), 13 DB7 (hiz), 14 DB6 (hiz), 15 DB5 (hiz), 16 DB4 (hiz), 17 DB3 (hiz), 18 DB2 (hiz), 19 DB1 (hiz), 20 DB0 (hiz), 21 P10 (io), 22 P11 (io), 23 P12 (io), 24 P13 (io), 25 P14 (io), 26 P15 (io), 27 P16 (io), 28 P17 (io), 29 P34 (out), 30 P33 (in), 31 P20 (io), 32 P21 (io), 33 P22 (io), 34 P23 (io), 35 P24 (io), 36 P25 (io), 37 P26 (io), 38 P27 (io), 39 P36 (out), 40 P31 (in)
2 alternate drawings of the same symbol

## Z8591UPC
designator U?
footprint DIP-64
pins: 1 P31 (in), 2 P36 (out), 3 P27 (io), 4 P26 (io), 5 P25 (io), 6 P24 (io), 7 P23 (io), 8 P22 (io), 9 P21 (io), 10 P20 (io), 11 P33 (in), 12 P34 (out), 13 P17 (io), 14 P16 (io), 15 P15 (io), 16 P14 (io), 17 P13 (io), 18 P12 (io), 19 P11 (io), 20 P10 (io), 21 D7 (in), 22 D6 (in), 23 D5 (in), 24 D4 (in), 25 A0 (out), 26 A1 (out), 27 A2 (out), 28 A3 (out), 29 A4 (out), 30 A5 (out), 31 A6 (out), 32 A7 (out), 33 A8 (out), 34 A9 (out), 35 A10 (out), 36 A11 (out), 37 D3 (in), 38 D2 (in), 39 D1 (in), 40 D0 (in), 41 IA/R~{W} (out), 42 MDS (out), 43 MAS (out), 44 SYNC (out), 45 DB0 (hiz), 46 DB1 (hiz), 47 DB2 (hiz), 48 GND (power) hidden to GND, 49 DB3 (hiz), 50 DB4 (hiz), 51 DB5 (hiz), 52 DB6 (hiz), 53 DB7 (hiz), 54 WAIT (oc), 55 CS (in), 56 ~{A}/D (in), 57 WR (in), 58 RD (in), 59 ~{A}/P32 (in), 60 ~{I}/P35 (out), 61 EI/P30 (in), 62 EO/P37 (out), 63 PCLK (in), 64 VCC (power) hidden to VCC
2 alternate drawings of the same symbol

## Z8601MCU
designator U?
footprint DIP-40
pins: 1 VCC (power) hidden to VCC, 2 XTAL2 (out), 3 XTAL1 (in), 4 P37 (out), 5 P30 (in), 6 RESET (in), 7 R/~{W} (out), 8 DS (out), 9 AS (out), 10 P35 (out), 11 GND (power) hidden to GND, 12 P32 (in), 13 P00A8 (io), 14 P01A9 (io), 15 P02A10 (io), 16 P03A11 (io), 17 P04A12 (io), 18 P05A13 (io), 19 P06A14 (io), 20 P07A15 (io), 21 P10AD0 (io), 22 P11AD1 (io), 23 P12AD2 (io), 24 P13AD3 (io), 25 P14AD4 (io), 26 P15AD5 (io), 27 P16AD6 (io), 28 P17AD7 (io), 29 P34 (out), 30 P33 (in), 31 P20 (io), 32 P21 (io), 33 P22 (io), 34 P23 (io), 35 P24 (io), 36 P25 (io), 37 P26 (io), 38 P27 (io), 39 P31 (in), 40 P36 (out)
2 alternate drawings of the same symbol

## Z8602MCU
designator U?
footprint DIP-64
pins: 1 P36 (out), 2 P31 (in), 3 P27 (io), 4 P26 (io), 5 P25 (io), 6 P24 (io), 7 P23 (io), 8 P22 (io), 9 P21 (io), 10 P20 (io), 11 P33 (in), 12 P34 (out), 13 P17 (io), 14 P16 (io), 15 P15 (io), 16 P14 (io), 17 P13 (io), 18 P12 (io), 19 P11 (io), 20 P10 (io), 21 D7 (in), 22 D6 (in), 23 D5 (in), 24 D4 (in), 25 A0 (out), 26 A1 (out), 27 A2 (out), 28 A3 (out), 29 A4 (out), 30 A5 (out), 31 A6 (out), 32 A7 (out), 33 A8 (out), 34 A9 (out), 35 A10 (out), 36 A11 (out), 37 D3 (in), 38 D2 (in), 39 D1 (in), 40 D0 (in), 41 MDS (out), 42 SCLK (out), 43 SYNC (out), 44 IACK (out), 45 P07 (io), 46 P06 (io), 47 P05 (io), 48 GND (power) hidden to GND, 49 P04 (io), 50 P03 (io), 51 P02 (io), 52 P01 (io), 53 P00 (io), 54 P32 (in), 55 P35 (out), 56 AS (out), 57 DS (out), 58 R/~{W} (out), 59 RESET (in), 60 P30 (in), 61 P37 (out), 62 XTAL1 (in), 63 XTAL2 (out), 64 VCC (power) hidden to VCC
2 alternate drawings of the same symbol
